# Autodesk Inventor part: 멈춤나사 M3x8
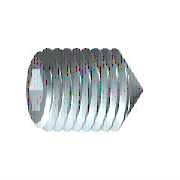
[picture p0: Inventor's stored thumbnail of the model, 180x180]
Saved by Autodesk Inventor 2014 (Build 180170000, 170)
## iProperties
Created: 2012-02
Part Number: 멈춤나사 M3x8
Material: 강철, 연강
Description: 6각 소켓 머리 없는 멈춤 나사
Document SubType Name: Modeling
Standard: KS B 1028
Designer: mduedu
Standards Organization: KS
Language: ko-KR
Size Designation: 원추점 M3x8
Categories: <MemberInstance><Categories><Category DisplayName="조임쇠" InternalName="e4da775c-781d-43d5-af7c-5136215cf5a6" Mnemonic="FSTN"><Category DisplayName="볼트" InternalN
Density: 7.86 g/cm^3
Mass: 0.360339 g
Surface Area: 0.888172 cm^2
Volume: 0.0458447 cm^3
Appearance: Steel
IsCustomPart: 1
Author: mduedu
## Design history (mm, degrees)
sketch "스케치1"
  geometry: L1 (0, 0)-(5.5, 0); L2 (8, 0.866)-(8, 1.5); L3 (8, 1.5)-(0, 1.5); L4 (8, 0.866)-(6, 0.866); L5 (6, 0.866)-(5.5, 0); L6 (0, -0.3)-(0, 1.8) reference; L7 (0, 1.5)-(0, 0)
  constraints: 13 end point, 3 parallel, 1 collinear, 1 perpendicular, 1 point on line
  dimensions: "d0" = 2 distance of L2.start L4.end (= INTI); "d1" = 60 deg angle of L5 L1; "d2" = 3 diameter of L3 L1 (= NND); "d3" = 1.73205 diameter of L4 L1 (= 1.1547 x SW); "d5" = 8 distance from line of L2 L3.end (= NLG)
revolve "본체" sketch "스케치1" stored, may be unused: angle "d6" = 90 deg
sketch "스케치2"
  geometry: L1 (-0.433, 0.75)-(0.433, 0.75); L2 (0.433, 0.75)-(0.866, 0); L3 (0.866, 0)-(0.433, -0.75); L4 (0.433, -0.75)-(-0.433, -0.75); L5 (-0.433, -0.75)-(-0.866, 0); L6 (-0.866, 0)-(-0.433, 0.75); 3 further points
  constraints: 12 end point, 1 coincident, 1 horizontal, 13 other
extrude "슬롯" join sketch "스케치2" taper "d7" = 0 deg; stored distance "d21" = 10
workaxis "Work Axis1"
workplane "Work Plane1"
sketch "스케치5"
  geometry: L1 (-4, -0.15)-(-2.65, -1.5) reference; L2 (-4, 0.15)-(-2.65, 1.5) reference; L3 (-2.65, 1.5)-(-4.15, 0); L4 (-2.65, -1.5)-(-4.15, 0); 1 further point
  constraints: 4 end point, 1 horizontal alignment, 1 perpendicular
node "작업점1"
body "Solid1"
feature "스레드" dims "d12" = 8 (= NLG), "d13" = 0
chamfer "모따기1" distance "d8" = 1.35 (computed from NND, SPD, FAWI); stored, may be unused: angle "d9" = 45 deg (= FAWI), second distance "d34" = 1.35 (computed from NND, SPD, FAWI)
chamfer "모따기2" distance "d10" = 0.30673 (= -0.5 x GD1 + 0.5 x NND); stored, may be unused: angle "d11" = 45 deg (= FAWI), second distance "d35" = 0.30673 (= -0.5 x GD1 + 0.5 x NND)
other parameters: "NND" = 3 [user parameter; used in 5 equation terms], "NLG" = 8 [user parameter; used in 2 equation terms], "INTI" = 2 [user parameter; used in 1 equation term], "FAWI" = 45 deg [user parameter; used in 4 equation terms], "SW" = 1.5 [user parameter; used in 2 equation terms], "GD1" = 2.38655 (= THREADDIA - 1.2269 x PTC) [user parameter; used in 2 equation terms], "d4" = 0, "FAWI1" = 45 deg [user parameter], "SPD" = 0.3 [user parameter; used in 2 equation terms], "d36" = 0, "d37" = 0, "GUL" = 0.30673 (= 0.61345 x PTC) [user parameter], "TOA" = 30 deg [user parameter], "THREADDIA" = 3 [user parameter; used in 1 equation term], "PTC" = 0.5 [user parameter; used in 4 equation terms], "GAL" = 0.30673 (= 0.61345 x PTC) [user parameter], "E0" = 1.7325 (= 1.155 x SW) [user parameter]
